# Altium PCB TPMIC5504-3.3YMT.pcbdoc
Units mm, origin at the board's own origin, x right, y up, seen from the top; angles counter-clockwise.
Board outline 14.13 x 13.97 mm, 2 copper layers (Top Layer, Bottom Layer), stack 0 mm thick; 1 components, 0 nets, 5 pads, 0 vias.
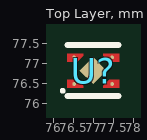
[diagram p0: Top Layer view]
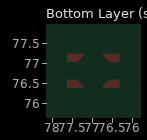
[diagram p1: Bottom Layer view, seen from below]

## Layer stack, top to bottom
Top Layer: signal copper (thickness not stored)
Bottom Layer: signal copper (thickness not stored)

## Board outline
83.984,69.85 69.85,69.85 69.85,83.82 83.984,83.82

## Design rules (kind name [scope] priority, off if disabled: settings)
PasteMaskExpansion "Paste Mask Expansion" [All] p1: expansion=0
SolderMaskExpansion "Solder Mask Expansion" [IsVia] p1: expansion=-25.4 istentingtop=TRUE
SolderMaskExpansion "Solder Mask Expansion" [All] p2: expansion=0.051 istentingtop=FALSE

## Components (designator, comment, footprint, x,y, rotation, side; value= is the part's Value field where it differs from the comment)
U? "TPMIC5504-3.3YMT" DFN-4_L1.0-W1.0-P0.65-BL-EP-2 76.984,76.831 r0 top

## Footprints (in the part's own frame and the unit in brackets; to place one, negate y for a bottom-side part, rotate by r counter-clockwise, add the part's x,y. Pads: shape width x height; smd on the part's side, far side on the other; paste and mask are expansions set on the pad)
DFN-4_L1.0-W1.0-P0.65-BL-EP-2 [mm]
  round 0.092 smd: 1(-0.475,-0.333) 2(0.475,-0.333) 3(0.475,0.333) 4(-0.474,0.333)
  rect 0.48x0.48 smd rot 135: 5(0.001,0.004)
  Top Layer region: -0.649,0.425 -0.649,0.225 -0.399,0.225 -0.399,0.225 -0.249,0.375 -0.249,0.425
  Top Layer region: 0.651,-0.425 0.651,-0.225 0.401,-0.225 0.401,-0.225 0.251,-0.375 0.251,-0.425
  Top Layer region: 0.651,0.425 0.651,0.225 0.401,0.225 0.401,0.225 0.251,0.375 0.251,0.425
  Top Layer region: -0.4,-0.225 -0.65,-0.225 -0.65,-0.425 -0.25,-0.425 -0.25,-0.375
  silkscreen extent -0.78,-0.63 0.64,0.64

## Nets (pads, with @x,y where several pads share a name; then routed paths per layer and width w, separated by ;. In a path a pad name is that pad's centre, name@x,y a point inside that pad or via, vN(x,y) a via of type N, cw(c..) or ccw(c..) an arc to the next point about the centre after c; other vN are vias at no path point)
pads on no net: U?.1 U?.2 U?.3 U?.4 U?.5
